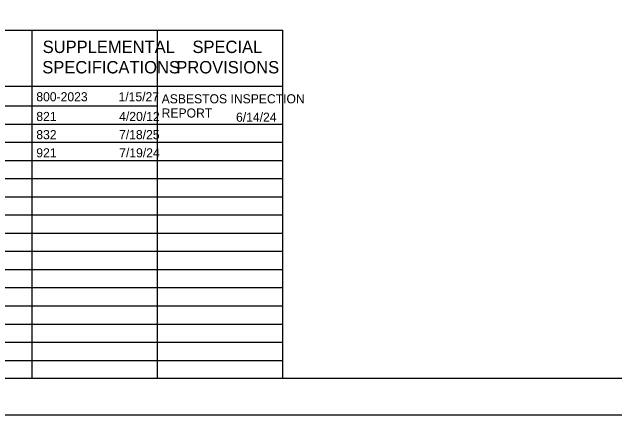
# Model space of a CAD drawing. Extents: x 0 to 34, y -5 to 22.
# Drawn here: x 19.87 to 28.17, y 0 to 5.54 of the extents above; entities that cross this region are included whole.
import ezdxf

# ---------------------------------------------------------------- set-up
doc = ezdxf.new("R2010")
doc.units = 0
for name, color, linetype in [('SH_Border', 7, 'Continuous'), ('SH_Cut_Line', 7, 'Continuous'), ('SH_Data', 7, 'Continuous'), ('SH_Text', 7, 'Continuous')]:
    doc.layers.add(name, color=color, linetype=linetype)

msp = doc.modelspace()

# ---------------------------------------------------------------- linework, layer by layer
at = {"layer": 'SH_Border'}
msp.add_lwpolyline([(1.5, 21.5), (33.5, 21.5), (33.5, 0.5), (1.5, 0.5)], close=True, dxfattribs=at)
at = {"layer": 'SH_Cut_Line'}
msp.add_lwpolyline([(0, 0), (34, 0), (34, 22), (0, 22)], close=True, dxfattribs=at)
at = {"layer": 'SH_Data'}
for p, q in [((10.15, 5.2917), (23.6, 5.2917)), ((20.15, 0.5), (20.15, 5.2917)), ((21.875, 0.5), (21.875, 5.2917)), ((23.6, 0.5), (23.6, 5.2917)), ((10.15, 4.5209), (23.6, 4.5209)), ((10.15, 4.25), (21.875, 4.25)), ((10.15, 4), (23.6, 4)), ((10.15, 3.75), (23.6, 3.75)), ((10.15, 3.5), (23.6, 3.5)), ((10.15, 3.25), (23.6, 3.25)), ((10.15, 3), (23.6, 3)), ((10.15, 2.75), (23.6, 2.75)), ((10.15, 2.5), (23.6, 2.5)), ((10.15, 2.25), (23.6, 2.25)), ((10.15, 2), (23.6, 2)), ((10.15, 1.75), (23.6, 1.75)), ((10.15, 1.5), (23.6, 1.5)), ((10.15, 1.25), (23.6, 1.25)), ((10.15, 1), (23.6, 1)), ((10.15, 0.75), (23.6, 0.75))]:
    msp.add_line(p, q, dxfattribs=at)

# ---------------------------------------------------------------- texts
at = {"layer": 'SH_Text'}
for s, height, p in [('SUPPLEMENTAL', 0.17, (20.2925, 4.9763)), ('SPECIAL', 0.17, (22.3542, 4.9763)), ('SPECIFICATIONS', 0.17, (20.2871, 4.6963)), ('PROVISIONS', 0.17, (22.1323, 4.6963)), ('800-2023', 0.125, (20.205, 4.3125)), ('1/15/27', 0.125, (21.3367, 4.3125)), ('ASBESTOS INSPECTION ', 0.125, (21.93, 4.2844)), ('821', 0.125, (20.205, 4.0416)), ('4/20/12', 0.125, (21.3455, 4.0416)), ('REPORT', 0.125, (21.93, 4.0894)), ('6/14/24', 0.125, (22.9541, 4.0316)), ('832', 0.125, (20.205, 3.7916)), ('7/18/25', 0.125, (21.3439, 3.7916)), ('921', 0.125, (20.205, 3.5416)), ('7/19/24', 0.125, (21.346, 3.5416))]:
    msp.add_text(s, height=height, dxfattribs=at).set_placement(p)

doc.saveas('drawing.dxf')
